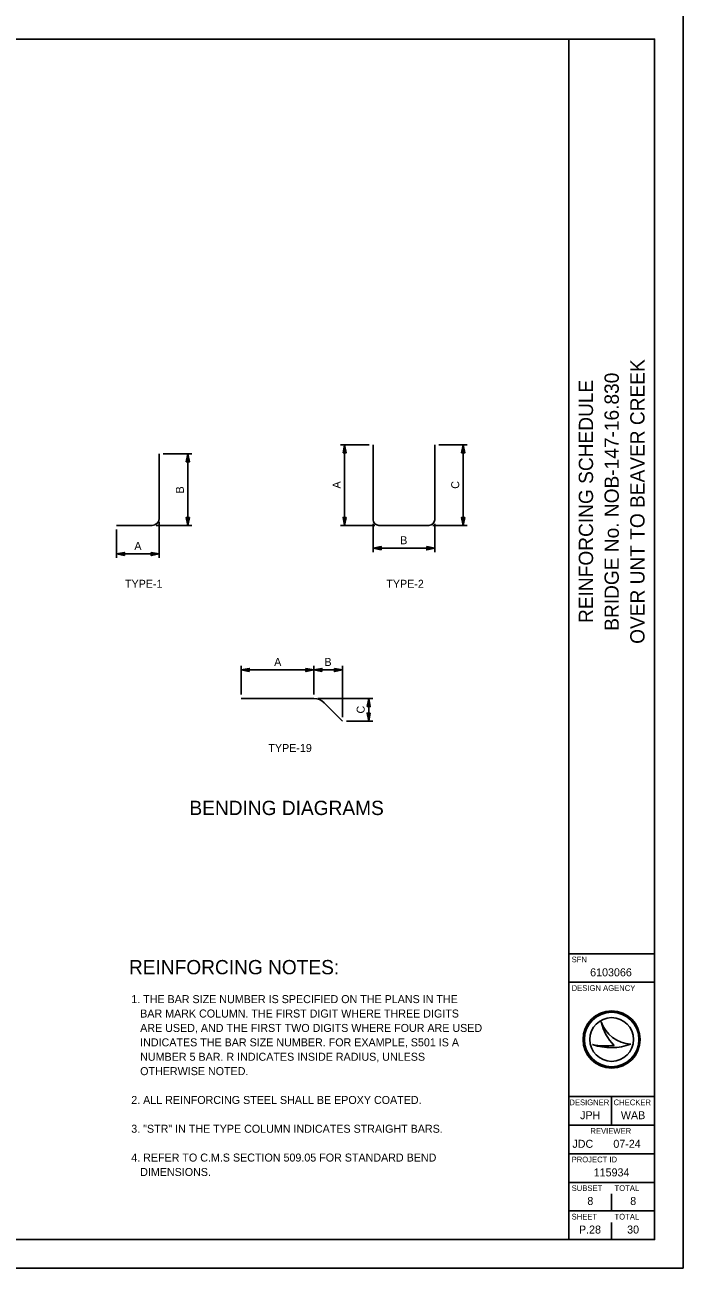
# Model space of a CAD drawing. Extents: x -309 to 121, y -132 to 101.
# Drawn here: x 67.5 to 102, y -132 to -66.7 of the extents above; entities that cross this region are included whole.
import ezdxf

# ---------------------------------------------------------------- set-up
doc = ezdxf.new("R2010")
doc.units = 0
for name, color, linetype in [('BR_P_Gen_NonPerf_Pipe', 7, 'Continuous'), ('BR_P_Gen_Text', 7, 'Continuous'), ('SH_Border', 7, 'Continuous'), ('SH_Cut_Line', 7, 'Continuous'), ('SH_Data', 7, 'Continuous'), ('TX_P_10', 7, 'Continuous')]:
    doc.layers.add(name, color=color, linetype=linetype)

msp = doc.modelspace()

# ---------------------------------------------------------------- linework, layer by layer
at = {"layer": 'BR_P_Gen_Text'}
for p, q in [((74.511, -92.643), (74.511, -89.268)), ((74.721, -89.268), (76.221, -89.268)), ((76.011, -89.268), (76.011, -93.018)), ((85.525, -88.786), (84.025, -88.786)), ((84.235, -88.786), (84.235, -93.018)), ((85.735, -88.786), (85.735, -92.718)), ((88.96, -92.718), (88.96, -88.786)), ((89.17, -88.786), (90.669, -88.786)), ((90.459, -88.786), (90.459, -93.018)), ((72.261, -93.018), (74.136, -93.018)), ((72.261, -93.227), (72.261, -94.727)), ((74.346, -93.018), (76.221, -93.018)), ((74.511, -92.853), (74.511, -94.727)), ((85.825, -93.018), (84.025, -93.018)), ((85.735, -92.928), (85.735, -94.427)), ((86.035, -93.018), (88.66, -93.018)), ((88.87, -93.018), (90.669, -93.018)), ((88.96, -92.928), (88.96, -94.427)), ((72.261, -94.517), (74.511, -94.517)), ((85.735, -94.217), (88.96, -94.217)), ((78.813, -101.894), (78.813, -100.394)), ((82.627, -101.894), (82.627, -100.394)), ((82.627, -101.894), (82.627, -100.394)), ((84.12, -103.076), (84.12, -100.394)), ((82.627, -100.604), (78.813, -100.604)), ((82.627, -100.604), (84.12, -100.604)), ((82.627, -102.104), (78.813, -102.104)), ((82.837, -102.104), (85.708, -102.104)), ((83.157, -102.323), (84.12, -103.286)), ((85.498, -103.286), (85.498, -102.104)), ((84.33, -103.286), (85.708, -103.286))]:
    msp.add_line(p, q, dxfattribs=at)
for points in [[(75.927, -89.688), (76.011, -89.268), (76.095, -89.688)], [(84.151, -89.206), (84.235, -88.786), (84.319, -89.206)], [(90.375, -89.206), (90.459, -88.786), (90.543, -89.206)], [(76.095, -92.598), (76.011, -93.018), (75.927, -92.598)], [(84.319, -92.598), (84.235, -93.018), (84.151, -92.598)], [(90.543, -92.598), (90.459, -93.018), (90.375, -92.598)], [(72.681, -94.601), (72.261, -94.517), (72.681, -94.433)], [(74.091, -94.433), (74.511, -94.517), (74.091, -94.601)], [(86.155, -94.301), (85.735, -94.217), (86.155, -94.133)], [(88.54, -94.133), (88.96, -94.217), (88.54, -94.301)], [(79.233, -100.688), (78.813, -100.604), (79.233, -100.52)], [(82.207, -100.52), (82.627, -100.604), (82.207, -100.688)], [(83.047, -100.688), (82.627, -100.604), (83.047, -100.52)], [(83.7, -100.52), (84.12, -100.604), (83.7, -100.688)], [(85.414, -102.523), (85.498, -102.104), (85.582, -102.523)], [(85.582, -102.866), (85.498, -103.286), (85.414, -102.866)]]:
    msp.add_lwpolyline(points, close=True, dxfattribs=at)
for centre, radius, start, end in [((74.136, -92.643), 0.375, 270, 360), ((86.035, -92.718), 0.3, 180, 270), ((88.66, -92.718), 0.3, 270, 360), ((82.627, -102.853), 0.75, 45, 90)]:
    msp.add_arc(centre, radius, start, end, dxfattribs=at)
at = {"layer": 'SH_Border'}
for p, q in [((95.995, -130.497), (95.995, -67.5)), ((95.995, -115.498), (100.495, -115.498)), ((95.995, -116.997), (100.495, -116.997)), ((95.995, -122.997), (100.495, -122.997)), ((98.245, -122.997), (98.245, -124.497)), ((95.995, -124.497), (100.495, -124.497)), ((95.995, -125.997), (100.495, -125.997)), ((95.995, -127.497), (100.495, -127.497)), ((95.995, -128.997), (100.495, -128.997))]:
    msp.add_line(p, q, dxfattribs=at)
msp.add_lwpolyline([(4.5, -67.5), (100.495, -67.5), (100.495, -130.497), (4.5, -130.497)], close=True, dxfattribs=at)
at = {"layer": 'SH_Cut_Line'}
msp.add_lwpolyline([(0, -131.997), (101.995, -131.997), (101.995, -66), (0, -66)], close=True, dxfattribs=at)
at = {"layer": 'SH_Data'}
for p, q in [((97.697, -119.069), (97.697, -119.069)), ((98.245, -119.997), (98.245, -119.997)), ((97.247, -120.269), (97.247, -120.269)), ((99.257, -120.242), (99.257, -120.242)), ((98.245, -128.997), (98.245, -128.097)), ((98.245, -130.497), (98.245, -129.597)), ((97.12, -129.972), (97.12, -129.972))]:
    msp.add_line(p, q, dxfattribs=at)
for radius in [1.5, 1.43, 1.43, 1.147]:
    msp.add_circle((98.245, -119.997), radius, dxfattribs=at)
for centre, radius, start, end in [((99.343, -118.504), 1.739, 198.92567, 198.93195), ((100.035, -118.587), 2.387, 191.63793, 191.64215), ((99.343, -118.504), 1.739, 198.93195, 267.16574), ((100.035, -118.587), 2.387, 191.64215, 226.09467), ((98.213, -117.387), 3.039, 251.45764, 290.08324), ((97.939, -116.534), 3.798, 259.49639, 259.49952), ((98.213, -117.387), 3.039, 251.45274, 251.45764), ((97.939, -116.534), 3.798, 259.49952, 276.66723)]:
    msp.add_arc(centre, radius, start, end, dxfattribs=at)

# ---------------------------------------------------------------- texts
at = {"layer": 'BR_P_Gen_NonPerf_Pipe'}
for s, p in [('1. THE BAR SIZE NUMBER IS SPECIFIED ON THE PLANS IN THE', (73.041, -118.089)), ('   BAR MARK COLUMN. THE FIRST DIGIT WHERE THREE DIGITS', (73.041, -118.845)), ('   ARE USED, AND THE FIRST TWO DIGITS WHERE FOUR ARE USED ', (73.041, -119.601)), ('   INDICATES THE BAR SIZE NUMBER. FOR EXAMPLE, S501 IS A ', (73.041, -120.357)), ('   NUMBER 5 BAR. R INDICATES INSIDE RADIUS, UNLESS', (73.041, -121.113)), ('   OTHERWISE NOTED.', (73.041, -121.869)), ('2. ALL REINFORCING STEEL SHALL BE EPOXY COATED.', (73.041, -123.381)), ('3. "STR" IN THE TYPE COLUMN INDICATES STRAIGHT BARS.', (73.041, -124.892)), ('4. REFER TO C.M.S SECTION 509.05 FOR STANDARD BEND ', (73.041, -126.404)), ('   DIMENSIONS.', (73.041, -127.16))]:
    msp.add_text(s, height=0.41998, dxfattribs=at).set_placement(p)
at = {"layer": 'BR_P_Gen_Text'}
for s, p in [('B', (75.801, -91.339)), ('A', (84.025, -91.083)), ('C', (90.249, -91.096)), ('C', (85.288, -102.889))]:
    msp.add_text(s, height=0.42, rotation=90, dxfattribs=at).set_placement(p)
for s, p in [('A', (73.205, -94.307)), ('B', (87.151, -94.007)), ('A', (80.539, -100.394)), ('B', (83.177, -100.394))]:
    msp.add_text(s, height=0.42, dxfattribs=at).set_placement(p)
at = {"layer": 'SH_Data'}
for s, p in [('OVER UNT TO BEAVER CREEK', (99.97, -99.234)), ('REINFORCING SCHEDULE', (97.27, -98.137)), ('BRIDGE No. NOB-147-16.830', (98.62, -98.548))]:
    msp.add_text(s, height=0.74996, rotation=90, dxfattribs=at).set_placement(p)
for s, height, p in [('BENDING DIAGRAMS', 0.74996, (76.094, -108.218)), ('REINFORCING NOTES:', 0.74996, (72.92, -116.576)), ('SFN', 0.3, (96.145, -115.947)), ('6103066', 0.42, (97.117, -116.682)), ('DESIGN AGENCY', 0.29998, (96.145, -117.447)), ('DESIGNER', 0.3, (96.028, -123.447)), ('CHECKER', 0.3, (98.348, -123.447)), ('JPH', 0.42, (96.589, -124.182)), ('WAB', 0.42, (98.728, -124.182)), ('JDC', 0.42, (96.186, -125.682)), ('REVIEWER', 0.3, (97.13, -124.947)), ('07-24', 0.42, (98.334, -125.682)), ('PROJECT ID', 0.3, (96.145, -126.447)), ('115934', 0.42, (97.303, -127.182)), ('SUBSET', 0.3, (96.145, -127.947)), ('TOTAL', 0.3, (98.395, -127.947)), ('8', 0.42, (96.97, -128.682)), ('8', 0.42, (99.22, -128.682)), ('SHEET', 0.3, (96.145, -129.447)), ('TOTAL', 0.3, (98.395, -129.447)), ('P.28', 0.42, (96.53, -130.182)), ('30', 0.42, (99.058, -130.182))]:
    msp.add_text(s, height=height, dxfattribs=at).set_placement(p)
at = {"layer": 'TX_P_10'}
for s, p in [('TYPE-1', (72.713, -96.293)), ('TYPE-2', (86.424, -96.293)), ('TYPE-19', (80.235, -104.911))]:
    msp.add_text(s, height=0.42, dxfattribs=at).set_placement(p)

doc.saveas('drawing.dxf')
